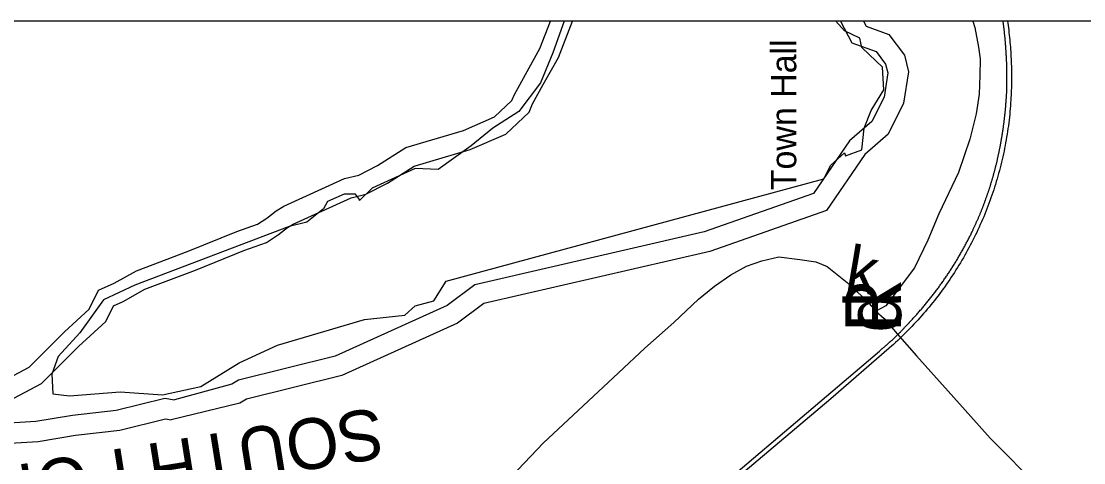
# Model space of a CAD drawing. Extents: x 1372027 to 1374286, y 553832 to 556743.
# Drawn here: x 1373346.9 to 1373419, y 554361.5 to 554391.5 of the extents above; entities that cross this region are included whole.
import ezdxf

# ---------------------------------------------------------------- set-up
doc = ezdxf.new("R2010")
doc.units = 0
for name, color, linetype in [('Old_Level_44', 7, 'Continuous'), ('Prop Dimension', 7, 'Continuous'), ('Prop Dimension Text', 7, 'Continuous'), ('Prop Lane Arrow CELL', 7, 'Continuous'), ('Prop Paved Shoulder', 7, 'Continuous'), ('Prop Terminator CELL', 7, 'Continuous'), ('Sheet Clip Boundary CELL', 7, 'Continuous'), ('Sheet North Arrow Point CELL', 7, 'Continuous'), ('Sheet Plot Border Outside CELL', 7, 'Continuous'), ('Sheet Sticker Incomplete CELL', 7, 'Continuous')]:
    doc.layers.add(name, color=color, linetype=linetype)

msp = doc.modelspace()

# ---------------------------------------------------------------- linework, layer by layer
at = {"layer": 'Old_Level_44'}
for points in [[(1373413.57, 554391.262), (1373413.563, 554391.31), (1373413.558, 554391.357), (1373413.552, 554391.402), (1373413.545, 554391.449), (1373413.539, 554391.497), (1373413.534, 554391.529)], [(1373413.836, 554391.529), (1373413.854, 554391.402), (1373413.877, 554391.239), (1373413.897, 554391.079), (1373413.917, 554390.916), (1373413.935, 554390.754), (1373413.953, 554390.59), (1373413.97, 554390.427), (1373413.987, 554390.265), (1373414.001, 554390.102), (1373414.016, 554389.94), (1373414.028, 554389.774), (1373414.04, 554389.611), (1373414.051, 554389.449), (1373414.061, 554389.286), (1373414.07, 554389.122), (1373414.078, 554388.958), (1373414.084, 554388.795), (1373414.09, 554388.631), (1373414.095, 554388.47), (1373414.1, 554388.304), (1373414.102, 554388.14), (1373414.105, 554387.979), (1373414.106, 554387.813), (1373414.105, 554387.649), (1373414.105, 554387.488), (1373414.102, 554387.322), (1373414.1, 554387.158), (1373414.095, 554386.997), (1373414.09, 554386.831), (1373414.083, 554386.668), (1373414.077, 554386.506), (1373414.068, 554386.342), (1373414.059, 554386.177)], [(1373413.778, 554386.648), (1373413.779, 554386.696), (1373413.781, 554386.743), (1373413.782, 554386.79), (1373413.783, 554386.833), (1373413.784, 554386.881), (1373413.785, 554386.928), (1373413.787, 554386.975), (1373413.788, 554387.023), (1373413.789, 554387.068), (1373413.791, 554387.115), (1373413.791, 554387.163), (1373413.793, 554387.21), (1373413.793, 554387.258), (1373413.794, 554387.301), (1373413.794, 554387.348), (1373413.795, 554387.395), (1373413.795, 554387.443), (1373413.795, 554387.488), (1373413.796, 554387.535), (1373413.796, 554387.583), (1373413.796, 554387.63), (1373413.796, 554387.677), (1373413.796, 554387.72), (1373413.796, 554387.768), (1373413.796, 554387.815), (1373413.795, 554387.863), (1373413.795, 554387.91), (1373413.795, 554387.955), (1373413.795, 554388.002), (1373413.794, 554388.05), (1373413.794, 554388.097), (1373413.793, 554388.145), (1373413.791, 554388.188), (1373413.791, 554388.235), (1373413.789, 554388.282), (1373413.788, 554388.33), (1373413.787, 554388.375), (1373413.787, 554388.422), (1373413.785, 554388.47), (1373413.784, 554388.517), (1373413.783, 554388.564), (1373413.781, 554388.607), (1373413.779, 554388.655), (1373413.778, 554388.702), (1373413.777, 554388.75), (1373413.773, 554388.795), (1373413.772, 554388.842), (1373413.77, 554388.89), (1373413.769, 554388.937), (1373413.766, 554388.984), (1373413.765, 554389.029), (1373413.762, 554389.075), (1373413.759, 554389.122), (1373413.757, 554389.169), (1373413.754, 554389.215), (1373413.753, 554389.262), (1373413.75, 554389.309), (1373413.746, 554389.357), (1373413.743, 554389.402), (1373413.741, 554389.449), (1373413.739, 554389.497), (1373413.736, 554389.542), (1373413.731, 554389.587), (1373413.729, 554389.634), (1373413.725, 554389.682), (1373413.723, 554389.729), (1373413.718, 554389.774), (1373413.716, 554389.822), (1373413.712, 554389.869), (1373413.708, 554389.917), (1373413.704, 554389.96), (1373413.701, 554390.007), (1373413.698, 554390.054), (1373413.694, 554390.102), (1373413.689, 554390.147), (1373413.685, 554390.194), (1373413.681, 554390.242), (1373413.676, 554390.287), (1373413.673, 554390.332), (1373413.669, 554390.379), (1373413.664, 554390.427), (1373413.659, 554390.472), (1373413.654, 554390.519), (1373413.651, 554390.567), (1373413.645, 554390.612), (1373413.64, 554390.659), (1373413.636, 554390.707), (1373413.631, 554390.75), (1373413.626, 554390.797), (1373413.621, 554390.845), (1373413.615, 554390.892), (1373413.61, 554390.937), (1373413.604, 554390.984), (1373413.599, 554391.032), (1373413.594, 554391.077), (1373413.587, 554391.122), (1373413.582, 554391.17), (1373413.577, 554391.215), (1373413.57, 554391.262)], [(1373413.064, 554381.774), (1373413.075, 554381.821), (1373413.087, 554381.871), (1373413.098, 554381.918), (1373413.11, 554381.967), (1373413.121, 554382.015), (1373413.132, 554382.064), (1373413.144, 554382.112), (1373413.154, 554382.161), (1373413.165, 554382.209), (1373413.177, 554382.258), (1373413.187, 554382.306), (1373413.197, 554382.355), (1373413.208, 554382.402), (1373413.219, 554382.452), (1373413.229, 554382.499), (1373413.239, 554382.551), (1373413.25, 554382.6), (1373413.261, 554382.648), (1373413.27, 554382.697), (1373413.28, 554382.745), (1373413.29, 554382.794), (1373413.3, 554382.844), (1373413.309, 554382.891), (1373413.32, 554382.941), (1373413.329, 554382.99), (1373413.338, 554383.038), (1373413.347, 554383.087), (1373413.357, 554383.134), (1373413.365, 554383.186), (1373413.375, 554383.236), (1373413.384, 554383.285), (1373413.393, 554383.333), (1373413.401, 554383.382), (1373413.411, 554383.432), (1373413.419, 554383.479), (1373413.428, 554383.528), (1373413.436, 554383.578), (1373413.444, 554383.625), (1373413.453, 554383.677), (1373413.46, 554383.727), (1373413.47, 554383.776), (1373413.477, 554383.823), (1373413.485, 554383.873), (1373413.491, 554383.922), (1373413.5, 554383.972), (1373413.507, 554384.019), (1373413.515, 554384.069), (1373413.521, 554384.121), (1373413.53, 554384.17), (1373413.538, 554384.22), (1373413.544, 554384.267), (1373413.551, 554384.316), (1373413.558, 554384.366), (1373413.566, 554384.416), (1373413.572, 554384.467), (1373413.579, 554384.515), (1373413.585, 554384.564), (1373413.591, 554384.614), (1373413.598, 554384.663), (1373413.604, 554384.713), (1373413.61, 554384.762), (1373413.616, 554384.81), (1373413.623, 554384.859), (1373413.628, 554384.911), (1373413.634, 554384.96), (1373413.64, 554385.01), (1373413.645, 554385.059), (1373413.652, 554385.109), (1373413.657, 554385.158), (1373413.662, 554385.206), (1373413.668, 554385.257), (1373413.673, 554385.307), (1373413.678, 554385.356), (1373413.682, 554385.406), (1373413.687, 554385.455), (1373413.693, 554385.505), (1373413.697, 554385.557), (1373413.701, 554385.606), (1373413.706, 554385.656), (1373413.711, 554385.703), (1373413.715, 554385.753), (1373413.718, 554385.802), (1373413.724, 554385.852), (1373413.728, 554385.901), (1373413.731, 554385.953), (1373413.736, 554386.002), (1373413.74, 554386.052), (1373413.742, 554386.101), (1373413.746, 554386.151), (1373413.75, 554386.2), (1373413.753, 554386.252), (1373413.757, 554386.302), (1373413.759, 554386.351), (1373413.764, 554386.401), (1373413.766, 554386.45), (1373413.769, 554386.498), (1373413.771, 554386.547), (1373413.776, 554386.599), (1373413.778, 554386.648)], [(1373414.059, 554386.177), (1373414.047, 554385.983), (1373414.033, 554385.791), (1373414.017, 554385.598), (1373413.999, 554385.404), (1373413.981, 554385.21), (1373413.961, 554385.014), (1373413.939, 554384.822), (1373413.915, 554384.629), (1373413.891, 554384.437), (1373413.865, 554384.243), (1373413.836, 554384.052), (1373413.807, 554383.86), (1373413.776, 554383.666), (1373413.742, 554383.475), (1373413.708, 554383.283), (1373413.673, 554383.094), (1373413.636, 554382.902), (1373413.597, 554382.71), (1373413.557, 554382.521), (1373413.515, 554382.329), (1373413.472, 554382.14), (1373413.428, 554381.952), (1373413.38, 554381.763), (1373413.333, 554381.573), (1373413.282, 554381.384), (1373413.233, 554381.199), (1373413.18, 554381.012), (1373413.126, 554380.822), (1373413.071, 554380.637), (1373413.015, 554380.45), (1373412.956, 554380.267), (1373412.897, 554380.079), (1373412.836, 554379.896), (1373412.772, 554379.713), (1373412.708, 554379.528), (1373412.642, 554379.345), (1373412.575, 554379.162), (1373412.507, 554378.979), (1373412.437, 554378.798), (1373412.365, 554378.617), (1373412.293, 554378.436), (1373412.219, 554378.258), (1373412.142, 554378.077), (1373412.066, 554377.898), (1373411.987, 554377.722), (1373411.908, 554377.545), (1373411.826, 554377.369), (1373411.743, 554377.192), (1373411.658, 554377.015), (1373411.573, 554376.841), (1373411.486, 554376.667), (1373411.399, 554376.494), (1373411.308, 554376.32), (1373411.217, 554376.15), (1373411.124, 554375.98), (1373411.03, 554375.81), (1373410.935, 554375.638), (1373410.838, 554375.47), (1373410.741, 554375.302), (1373410.641, 554375.134), (1373410.539, 554374.968), (1373410.438, 554374.8), (1373410.335, 554374.639), (1373410.231, 554374.473), (1373410.125, 554374.309), (1373410.017, 554374.148), (1373409.909, 554373.988), (1373409.8, 554373.825), (1373409.688, 554373.667), (1373409.576, 554373.506), (1373409.462, 554373.349), (1373409.348, 554373.192), (1373409.232, 554373.037), (1373409.114, 554372.879), (1373408.995, 554372.727), (1373408.875, 554372.572), (1373408.755, 554372.421), (1373408.633, 554372.27), (1373408.509, 554372.117), (1373408.384, 554371.969), (1373408.258, 554371.822), (1373408.131, 554371.674), (1373408.004, 554371.527), (1373407.874, 554371.383), (1373407.744, 554371.239), (1373407.611, 554371.095), (1373407.479, 554370.953), (1373407.345, 554370.81), (1373407.21, 554370.673), (1373407.073, 554370.533), (1373406.937, 554370.393), (1373406.8, 554370.257), (1373406.659, 554370.124), (1373406.519, 554369.986), (1373406.377, 554369.854), (1373406.234, 554369.721), (1373406.09, 554369.59), (1373405.946, 554369.463), (1373405.801, 554369.333)], [(1373411.429, 554377.235), (1373411.449, 554377.278), (1373411.471, 554377.321), (1373411.491, 554377.366), (1373411.513, 554377.409), (1373411.533, 554377.455), (1373411.555, 554377.5), (1373411.574, 554377.541), (1373411.596, 554377.586), (1373411.616, 554377.631), (1373411.635, 554377.674), (1373411.656, 554377.72), (1373411.676, 554377.765), (1373411.696, 554377.81), (1373411.716, 554377.853), (1373411.736, 554377.898), (1373411.755, 554377.943), (1373411.775, 554377.989), (1373411.795, 554378.032), (1373411.814, 554378.077), (1373411.833, 554378.122), (1373411.854, 554378.165), (1373411.872, 554378.21), (1373411.892, 554378.256), (1373411.91, 554378.301), (1373411.929, 554378.348), (1373411.949, 554378.391), (1373411.967, 554378.436), (1373411.986, 554378.482), (1373412.005, 554378.527), (1373412.023, 554378.572), (1373412.041, 554378.617), (1373412.06, 554378.663), (1373412.078, 554378.708), (1373412.095, 554378.755), (1373412.113, 554378.798), (1373412.132, 554378.843), (1373412.149, 554378.889), (1373412.167, 554378.936), (1373412.184, 554378.979), (1373412.202, 554379.024), (1373412.22, 554379.072), (1373412.237, 554379.117), (1373412.254, 554379.164), (1373412.271, 554379.207), (1373412.288, 554379.252), (1373412.305, 554379.3), (1373412.322, 554379.345), (1373412.338, 554379.392), (1373412.355, 554379.438), (1373412.372, 554379.485), (1373412.388, 554379.528), (1373412.405, 554379.575), (1373412.42, 554379.621), (1373412.436, 554379.668), (1373412.454, 554379.715), (1373412.47, 554379.761), (1373412.485, 554379.806), (1373412.501, 554379.851), (1373412.516, 554379.898), (1373412.532, 554379.944), (1373412.548, 554379.991), (1373412.562, 554380.038), (1373412.578, 554380.081), (1373412.592, 554380.129), (1373412.609, 554380.176), (1373412.623, 554380.221), (1373412.639, 554380.269), (1373412.653, 554380.316), (1373412.668, 554380.363), (1373412.682, 554380.409), (1373412.696, 554380.456), (1373412.711, 554380.503), (1373412.725, 554380.551), (1373412.74, 554380.594), (1373412.754, 554380.641), (1373412.769, 554380.689), (1373412.782, 554380.736), (1373412.796, 554380.783), (1373412.809, 554380.831), (1373412.824, 554380.876), (1373412.837, 554380.923), (1373412.85, 554380.971), (1373412.863, 554381.018), (1373412.877, 554381.063), (1373412.89, 554381.111), (1373412.902, 554381.158), (1373412.915, 554381.205), (1373412.928, 554381.253), (1373412.941, 554381.3), (1373412.953, 554381.347), (1373412.967, 554381.395), (1373412.979, 554381.442), (1373412.992, 554381.49), (1373413.004, 554381.537), (1373413.015, 554381.584), (1373413.027, 554381.632), (1373413.04, 554381.679), (1373413.052, 554381.726), (1373413.064, 554381.774)], [(1373407.379, 554371.303), (1373407.428, 554371.359), (1373407.478, 554371.411), (1373407.526, 554371.465), (1373407.575, 554371.519), (1373407.624, 554371.575), (1373407.674, 554371.626), (1373407.722, 554371.682), (1373407.77, 554371.738), (1373407.818, 554371.79), (1373407.866, 554371.846), (1373407.914, 554371.9), (1373407.961, 554371.956), (1373408.01, 554372.01), (1373408.057, 554372.066), (1373408.103, 554372.122), (1373408.15, 554372.178), (1373408.197, 554372.234), (1373408.244, 554372.29), (1373408.291, 554372.343), (1373408.336, 554372.402), (1373408.382, 554372.457), (1373408.428, 554372.516), (1373408.474, 554372.569), (1373408.52, 554372.628), (1373408.566, 554372.686), (1373408.61, 554372.74), (1373408.657, 554372.798), (1373408.701, 554372.856), (1373408.746, 554372.914), (1373408.79, 554372.972), (1373408.835, 554373.028), (1373408.878, 554373.086), (1373408.923, 554373.144), (1373408.968, 554373.202), (1373409.011, 554373.261), (1373409.054, 554373.319), (1373409.097, 554373.375), (1373409.141, 554373.435), (1373409.184, 554373.493), (1373409.226, 554373.553), (1373409.269, 554373.612), (1373409.311, 554373.672), (1373409.354, 554373.73), (1373409.396, 554373.79), (1373409.438, 554373.848), (1373409.479, 554373.909), (1373409.521, 554373.969), (1373409.563, 554374.029), (1373409.604, 554374.089), (1373409.645, 554374.148), (1373409.686, 554374.208), (1373409.728, 554374.268), (1373409.767, 554374.328), (1373409.807, 554374.391), (1373409.848, 554374.451), (1373409.887, 554374.511), (1373409.927, 554374.572), (1373409.968, 554374.632), (1373410.007, 554374.697), (1373410.046, 554374.757), (1373410.084, 554374.817), (1373410.124, 554374.88), (1373410.162, 554374.94), (1373410.201, 554375.002), (1373410.239, 554375.063), (1373410.277, 554375.127), (1373410.316, 554375.19), (1373410.353, 554375.25), (1373410.39, 554375.312), (1373410.429, 554375.375), (1373410.465, 554375.439), (1373410.502, 554375.502), (1373410.538, 554375.564), (1373410.575, 554375.629), (1373410.612, 554375.691), (1373410.647, 554375.754), (1373410.684, 554375.816), (1373410.719, 554375.881), (1373410.755, 554375.943), (1373410.79, 554376.006), (1373410.826, 554376.072), (1373410.861, 554376.135), (1373410.897, 554376.197), (1373410.931, 554376.264), (1373410.965, 554376.327), (1373411, 554376.389), (1373411.035, 554376.456), (1373411.067, 554376.518), (1373411.101, 554376.583), (1373411.136, 554376.649), (1373411.168, 554376.712), (1373411.202, 554376.779), (1373411.234, 554376.843), (1373411.267, 554376.906), (1373411.3, 554376.972), (1373411.333, 554377.037), (1373411.364, 554377.104), (1373411.396, 554377.168), (1373411.429, 554377.235)], [(1373405.133, 554369.133), (1373405.157, 554369.155), (1373405.183, 554369.176), (1373405.205, 554369.193), (1373405.231, 554369.215), (1373405.255, 554369.237), (1373405.28, 554369.254), (1373405.303, 554369.275), (1373405.328, 554369.297), (1373405.352, 554369.318), (1373405.375, 554369.336), (1373405.4, 554369.357), (1373405.424, 554369.379), (1373405.448, 554369.398), (1373405.472, 554369.42), (1373405.496, 554369.441), (1373405.52, 554369.458), (1373405.543, 554369.48), (1373405.567, 554369.501), (1373405.592, 554369.523), (1373405.615, 554369.542), (1373405.639, 554369.564), (1373405.663, 554369.585), (1373405.687, 554369.607), (1373405.71, 554369.626), (1373405.734, 554369.648), (1373405.758, 554369.669), (1373405.78, 554369.691), (1373405.804, 554369.71), (1373405.826, 554369.732), (1373405.85, 554369.753), (1373405.874, 554369.775), (1373405.898, 554369.794), (1373405.921, 554369.816), (1373405.944, 554369.837), (1373405.967, 554369.861), (1373405.991, 554369.882), (1373406.013, 554369.902), (1373406.036, 554369.923), (1373406.06, 554369.945), (1373406.083, 554369.969), (1373406.106, 554369.99), (1373406.129, 554370.009), (1373406.153, 554370.031), (1373406.174, 554370.055), (1373406.198, 554370.076), (1373406.22, 554370.098), (1373406.243, 554370.117), (1373406.267, 554370.141), (1373406.288, 554370.162), (1373406.311, 554370.186), (1373406.335, 554370.208), (1373406.357, 554370.229), (1373406.379, 554370.253), (1373406.401, 554370.272), (1373406.425, 554370.296), (1373406.448, 554370.317), (1373406.47, 554370.339), (1373406.492, 554370.363), (1373406.514, 554370.384), (1373406.537, 554370.408), (1373406.559, 554370.427), (1373406.581, 554370.451), (1373406.604, 554370.475), (1373406.626, 554370.496), (1373406.648, 554370.52), (1373406.669, 554370.541), (1373406.692, 554370.565), (1373406.714, 554370.584), (1373406.736, 554370.608), (1373406.759, 554370.632), (1373406.779, 554370.653), (1373406.802, 554370.677), (1373406.824, 554370.701), (1373406.845, 554370.722), (1373406.867, 554370.746), (1373406.889, 554370.769), (1373406.911, 554370.793), (1373406.933, 554370.813), (1373406.954, 554370.836), (1373406.975, 554370.86), (1373406.998, 554370.884), (1373407.018, 554370.905), (1373407.041, 554370.929), (1373407.061, 554370.953), (1373407.083, 554370.976), (1373407.105, 554371), (1373407.126, 554371.024), (1373407.147, 554371.047), (1373407.168, 554371.071), (1373407.189, 554371.092), (1373407.211, 554371.116), (1373407.232, 554371.14), (1373407.253, 554371.163), (1373407.274, 554371.187), (1373407.295, 554371.211), (1373407.316, 554371.235), (1373407.337, 554371.258), (1373407.358, 554371.282), (1373407.379, 554371.303)], [(1373360.427, 554331.261), (1373363.463, 554333.769), (1373366.986, 554336.758), (1373372.108, 554341.088), (1373389.687, 554355.997), (1373405.133, 554369.133)], [(1373405.801, 554369.333), (1373401.826, 554365.884), (1373394.131, 554359.393), (1373383.654, 554350.505), (1373375.715, 554343.777), (1373366.872, 554336.25), (1373363.36, 554333.309)]]:
    msp.add_lwpolyline(points, dxfattribs=at)
at = {"layer": 'Prop Dimension Text'}
msp.add_lwpolyline([(1373151.666, 554391.529), (1373151.666, 554060.529), (1373482.666, 554060.529), (1373482.666, 554391.529)], close=True, dxfattribs=at)
at = {"layer": 'Prop Lane Arrow CELL'}
for points in [[(1373354.564, 554373.601), (1373352.456, 554372.618), (1373350.839, 554370.371), (1373349.363, 554368.756), (1373348.942, 554367.562), (1373349.012, 554366.227), (1373350.136, 554366.087), (1373353.58, 554366.368), (1373356.461, 554366.157), (1373359.062, 554366.719), (1373361.662, 554368.334), (1373364.262, 554369.528), (1373370.165, 554371.284), (1373372.906, 554371.564), (1373373.609, 554372.197), (1373374.874, 554372.548), (1373375.717, 554373.882), (1373401.351, 554380.837), (1373401.843, 554381.75), (1373402.756, 554382.593), (1373402.826, 554382.382), (1373403.951, 554382.803), (1373404.091, 554384.278), (1373404.583, 554385.472), (1373405.427, 554386.876), (1373405.356, 554388.421), (1373404.443, 554389.264), (1373403.951, 554389.756), (1373403.81, 554390.388), (1373402.756, 554390.879), (1373402.165, 554391.529)], [(1373383.718, 554391.529), (1373382.967, 554389.394), (1373382.123, 554387.357), (1373380.648, 554385.391), (1373378.891, 554384.267), (1373377.415, 554383.073), (1373375.166, 554381.458), (1373373.62, 554381.529), (1373370.683, 554380.198), (1373369.84, 554379.355), (1373369.84, 554379.426), (1373369.559, 554379.777), (1373368.786, 554379.777), (1373367.661, 554379.285), (1373367.38, 554378.793), (1373366.256, 554377.881), (1373365.061, 554377.6), (1373354.564, 554373.601)]]:
    msp.add_lwpolyline(points, dxfattribs=at)
at = {"layer": 'Prop Paved Shoulder'}
for points in [[(1373411.475, 554391.529), (1373411.607, 554391.102), (1373411.854, 554389.767), (1373411.977, 554388.988), (1373411.946, 554387.844), (1373411.916, 554386.572), (1373411.7, 554385.237), (1373411.268, 554383.521), (1373410.497, 554381.264), (1373409.173, 554378.46), (1373408.42, 554376.675), (1373407.524, 554374.786), (1373405.569, 554372.194), (1373404.897, 554371.848)], [(1373373.78, 554353.503), (1373376.496, 554356.664), (1373377.614, 554357.949), (1373382.292, 554362.885), (1373387.424, 554367.65), (1373389.216, 554369.329), (1373391.171, 554371.071), (1373392.841, 554372.666), (1373393.941, 554373.548), (1373395.04, 554374.303), (1373396.099, 554374.891), (1373397.158, 554375.269), (1373398.299, 554375.521), (1373399.724, 554375.353), (1373400.824, 554375.185), (1373401.598, 554374.87), (1373402.942, 554373.779), (1373404.281, 554372.552), (1373404.897, 554371.848)], [(1373404.897, 554371.848), (1373405.467, 554371.354), (1373406.352, 554370.303), (1373407.646, 554368.815), (1373410.77, 554365.32), (1373412.661, 554363.219), (1373416.031, 554359.818), (1373417.118, 554357.882), (1373417.677, 554356.764)]]:
    msp.add_lwpolyline(points, dxfattribs=at)
at = {"layer": 'Prop Terminator CELL'}
for points in [[(1373345.634, 554365.547), (1373348.227, 554366.929), (1373350.129, 554368.83), (1373350.74, 554369.441), (1373352.597, 554371.141), (1373353.121, 554372.209), (1373353.782, 554372.509), (1373355.262, 554373.331), (1373358.696, 554374.635), (1373361.982, 554375.962), (1373363.521, 554376.501), (1373364.34, 554377.046), (1373364.943, 554377.514), (1373365.331, 554377.743), (1373369.265, 554379.545), (1373370.263, 554379.782), (1373371.74, 554380.535), (1373373.553, 554381.688), (1373377.355, 554382.824), (1373379.759, 554383.865), (1373381.351, 554385.362), (1373381.574, 554385.918), (1373382.304, 554387.244), (1373383.332, 554389.078), (1373384.288, 554391.529)], [(1373402.488, 554391.529), (1373403.258, 554390.072), (1373404.918, 554389.469), (1373405.559, 554388.615), (1373405.705, 554388.031), (1373405.449, 554386.378), (1373404.627, 554384.723), (1373403.112, 554383.399), (1373400.661, 554379.84), (1373393.24, 554377.227), (1373377.668, 554373.637), (1373375.773, 554372.218), (1373368.18, 554368.788), (1373361.606, 554367.157), (1373361.171, 554366.885), (1373357.27, 554365.829)], [(1373345.674, 554364.232), (1373347.854, 554364.364), (1373350.347, 554364.779), (1373353.314, 554365.124), (1373356.603, 554365.945), (1373357.27, 554365.829)]]:
    msp.add_lwpolyline(points, dxfattribs=at)
at = {"layer": 'Sheet Plot Border Outside CELL'}
msp.add_line((1373406.326, 554370.296), (1373406.326, 554370.296), dxfattribs=at)
at = {"layer": 'Sheet Sticker Incomplete CELL'}
for points in [[(1373345.29, 554366.925), (1373347.398, 554368.049), (1373349.155, 554369.804), (1373349.787, 554370.436), (1373351.474, 554371.981), (1373352.101, 554373.261), (1373353.162, 554373.741), (1373354.68, 554374.584), (1373358.194, 554375.918), (1373361.497, 554377.252), (1373362.902, 554377.744), (1373363.535, 554378.165), (1373364.167, 554378.657), (1373364.693, 554378.966), (1373368.815, 554380.854), (1373369.784, 554381.085), (1373371.056, 554381.733), (1373372.975, 554382.954), (1373376.883, 554384.121), (1373378.991, 554385.033), (1373380.185, 554386.157), (1373380.326, 554386.508), (1373381.099, 554387.913), (1373382.083, 554389.668), (1373382.809, 554391.529)], [(1373345.29, 554366.925), (1373347.398, 554368.049), (1373349.155, 554369.804), (1373349.787, 554370.436), (1373351.474, 554371.981), (1373352.101, 554373.261), (1373353.162, 554373.741), (1373354.68, 554374.584), (1373358.194, 554375.918), (1373361.497, 554377.252), (1373362.902, 554377.744), (1373363.535, 554378.165), (1373364.167, 554378.657), (1373364.693, 554378.966), (1373368.815, 554380.854), (1373369.784, 554381.085), (1373371.056, 554381.733), (1373372.975, 554382.954), (1373376.883, 554384.121), (1373378.991, 554385.033), (1373380.185, 554386.157), (1373380.326, 554386.508), (1373381.099, 554387.913), (1373382.083, 554389.668), (1373382.809, 554391.529)], [(1373404.046, 554391.529), (1373404.228, 554391.186), (1373405.774, 554390.624), (1373406.828, 554389.22), (1373407.109, 554388.096), (1373406.779, 554385.957), (1373405.74, 554383.865), (1373404.149, 554382.475), (1373401.542, 554378.689), (1373393.624, 554375.902), (1373378.262, 554372.36), (1373376.478, 554371.024), (1373368.633, 554367.481), (1373362.15, 554365.872), (1373361.711, 554365.598), (1373357.033, 554364.471)], [(1373404.046, 554391.529), (1373404.228, 554391.186), (1373405.774, 554390.624), (1373406.828, 554389.22), (1373407.109, 554388.096), (1373406.779, 554385.957), (1373405.74, 554383.865), (1373404.149, 554382.475), (1373401.542, 554378.689), (1373393.624, 554375.902), (1373378.262, 554372.36), (1373376.478, 554371.024), (1373368.633, 554367.481), (1373362.15, 554365.872), (1373361.711, 554365.598), (1373357.033, 554364.471)], [(1373345.691, 554362.852), (1373348.01, 554362.993), (1373350.539, 554363.414), (1373353.561, 554363.765), (1373356.653, 554364.538), (1373357.033, 554364.471)], [(1373345.691, 554362.852), (1373348.01, 554362.993), (1373350.539, 554363.414), (1373353.561, 554363.765), (1373356.653, 554364.538), (1373357.033, 554364.471)]]:
    msp.add_lwpolyline(points, dxfattribs=at)

# ---------------------------------------------------------------- texts
at = {"layer": 'Prop Dimension'}
msp.add_text('SOUTH FORK', height=3.4449, rotation=189.04387, dxfattribs=at).set_placement((1373371.153, 554365.321))
at = {"layer": 'Sheet Clip Boundary CELL'}
for s, p in [('R', (1373406.608, 554370.399)), ('d', (1373406.608, 554370.38))]:
    msp.add_text(s, height=3.789, rotation=90, dxfattribs=at).set_placement(p)
at = {"layer": 'Sheet North Arrow Point CELL'}
for s, height, rotation, p in [('Town Hall', 1.7224, 90, (1373399.488, 554380.058)), ('k', 3.1, 350.46694, (1373402.71, 554373.272))]:
    msp.add_text(s, height=height, rotation=rotation, dxfattribs=at).set_placement(p)

doc.saveas('drawing.dxf')
